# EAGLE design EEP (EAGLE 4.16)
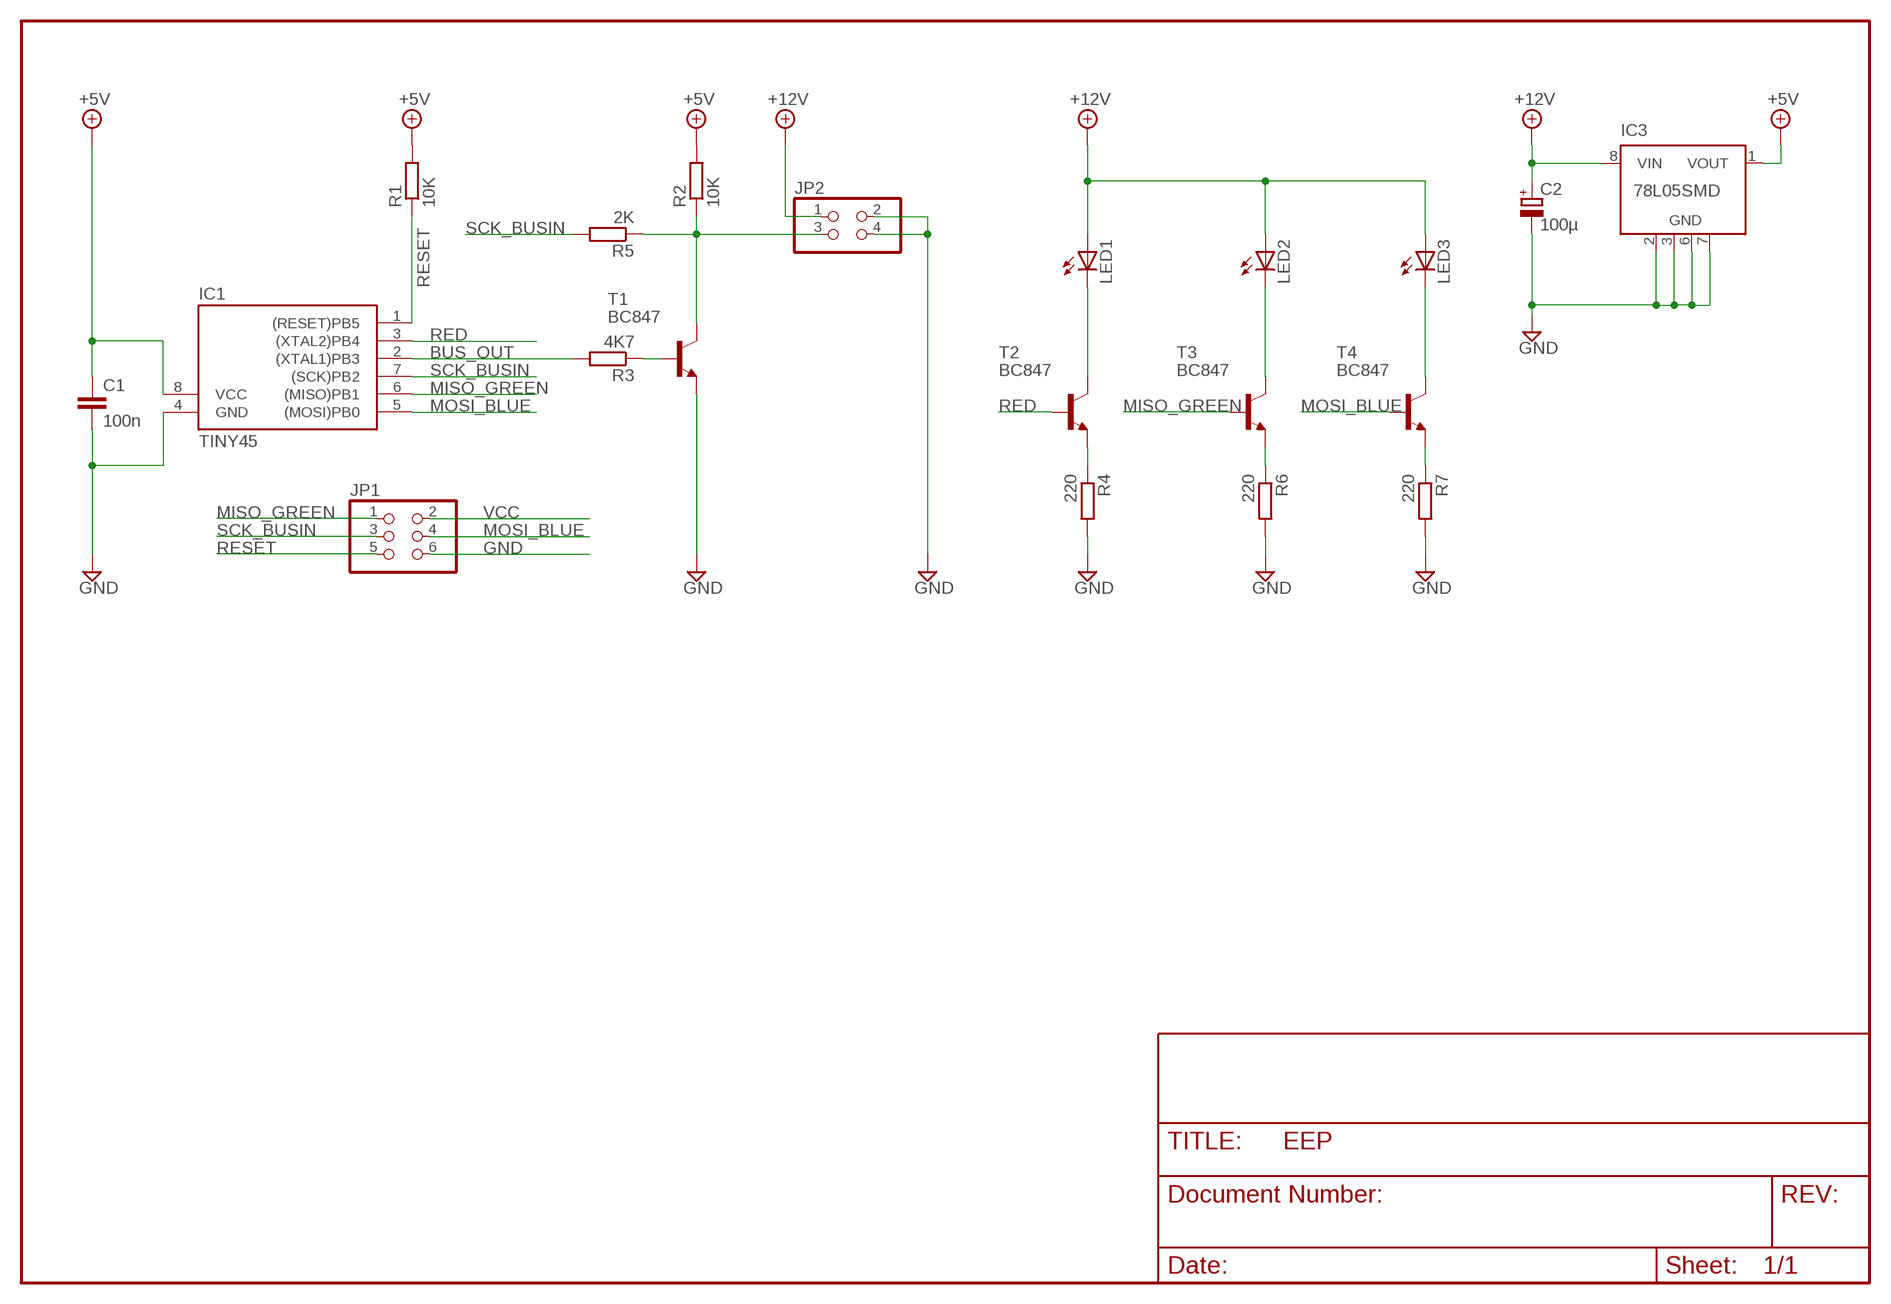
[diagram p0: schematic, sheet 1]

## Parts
C1  100n  C-EUC1206  [C1206]
C2  100µ  CPOL-EU153CLV-0605  [153CLV-0605]
IC1  TINY45  TINY12S  [SOIC8]
IC3  78L05SMD  [SO08]
JP1  PINHD-2X3_2.54-SMD  [2X03SMD]
JP2  PINHD-2X2_2.54-SMD  [2X02SMD]
LED1  LED5MM  [LED5MM]
LED2  LED5MM  [LED5MM]
LED3  LED5MM  [LED5MM]
R1  10K  R-EU_R1206  [R1206]
R2  10K  R-EU_R1206  [R1206]
R3  4K7  R-EU_R1206  [R1206]
R4  220  R-EU_R1206  [R1206]
R5  2K  R-EU_R1206  [R1206]
R6  220  R-EU_R1206  [R1206]
R7  220  R-EU_R1206  [R1206]
T1  BC847  [SOT23]
T2  BC847  [SOT23]
T3  BC847  [SOT23]
T4  BC847  [SOT23]

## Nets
+12V: C2.+ IC3.8(VIN) JP2.1 LED1.A LED2.A LED3.A
BUS_OUT: IC1.2((XTAL1)PB3) R3.2
GND: C1.2 C2.- IC1.4(GND) IC3.2(GND) IC3.3(GND) IC3.6(GND) IC3.7(GND) JP1.6 JP2.2 JP2.4 R4.2 R6.2 R7.2 T1.2(E)
MISO_GREEN: IC1.6((MISO)PB1) JP1.1 T3.1(B)
MOSI_BLUE: IC1.5((MOSI)PB0) JP1.4 T4.1(B)
N$1: LED1.K(C) T2.3(C)
N$2: R4.1 T2.2(E)
N$3: JP2.3 R2.1 R5.1 T1.3(C)
N$4: R6.1 T3.2(E)
N$5: R3.1 T1.1(B)
N$6: R7.1 T4.2(E)
N$7: LED3.K(C) T4.3(C)
N$8: LED2.K(C) T3.3(C)
RED: IC1.3((XTAL2)PB4) T2.1(B)
RESET: IC1.1((RESET)PB5) JP1.5 R1.1
SCK_BUSIN: IC1.7((SCK)PB2) JP1.3 R5.2
VCC: C1.1 IC1.8(VCC) IC3.1(VOUT) JP1.2 R1.2 R2.2 ; supply symbol labelled +5V
Unconnected: IC3.4(NC) IC3.5(NC)

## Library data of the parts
C1 = rcl:C-EU: CAPACITOR, European symbol
C2 = rcl:CPOL-EU: POLARIZED CAPACITOR, European symbol
IC1 = avr-1:TINY12*: MICROCONTROLLER 1 Kbytes FLASH 64 bytes EEPROM
IC3 = linear:78L*SMD: Positive VOLTAGE REGULATOR
JP1 = pinhead-1:PINHD-2X3: PIN HEADER
JP2 = pinhead-1:PINHD-2X2: PIN HEADER
LED1-LED3 = led:LED: LED
R1-R7 = rcl:R-EU_: RESISTOR, European symbol
T1-T4 = transistor:BC847: NPN TRANSISTOR

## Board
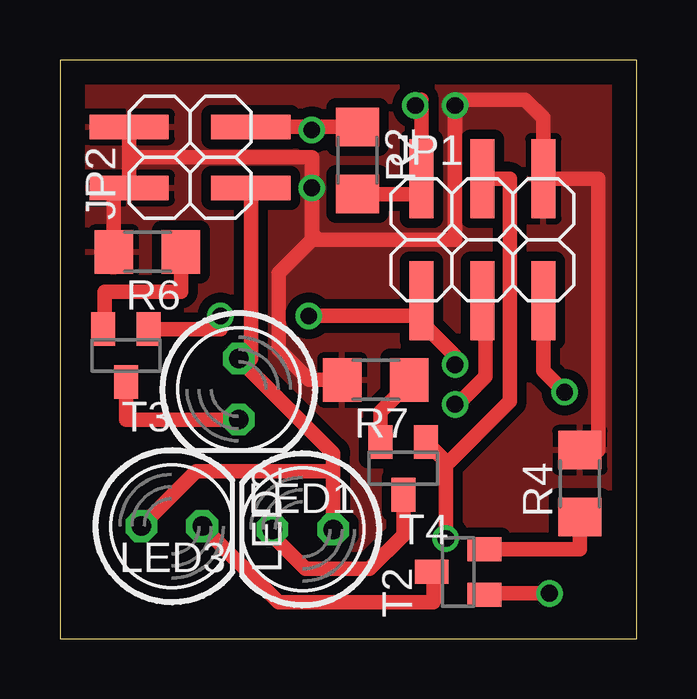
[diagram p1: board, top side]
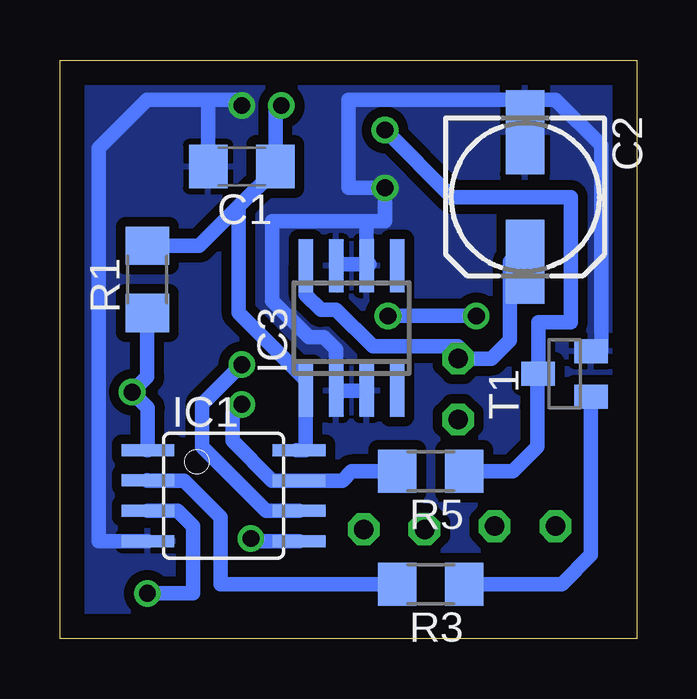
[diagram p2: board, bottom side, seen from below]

Size 24.05 x 24.12 mm. Coordinates in mm from the lower left corner, seen from the top.
Outline: 0,0 24.05,0 24.05,24.12 0,24.12 0,0
Copper layers (1*16): Top 0.035mm / dielectric 1.5mm / Bottom 0.035mm
Design rules "default": minimum track width 10mil, minimum drill 24mil, track to track 16mil, track to pad 12mil, pad to pad 12mil, via to via 12mil, smd to smd 8mil, copper to edge 40mil, drill to drill 8mil, minimum pad ring 10mil, minimum via ring 8mil, stop-mask expansion 4mil, vias tented up to drill 0mil, thermal gap 10mil

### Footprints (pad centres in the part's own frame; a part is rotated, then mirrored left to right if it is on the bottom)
C1206 = smd 1.6 x 1.8: 1 -1.4,0; 2 1.4,0
153CLV-0605 = smd 3.5 x 1.6: + 2.7,0; - -2.7,0
SOIC8 = smd 0.5 x 2.2: 1 -1.905,-3.154; 2 -0.645,-3.154; 3 0.625,-3.154; 4 1.895,-3.154; 5 1.905,3.154; 6 0.635,3.154; 7 -0.635,3.154; 8 -1.905,3.154
SO08 = smd 0.6 x 2.2: 1 -1.905,-2.6; 2 -0.635,-2.6; 3 0.635,-2.6; 4 1.905,-2.6; 5 1.905,2.6; 6 0.635,2.6; 7 -0.635,2.6; 8 -1.905,2.6
2X03SMD = smd 1.016 x 3.302: 1 -1.27,-3.81; 2 -1.27,1.27; 3 1.27,-3.81; 4 1.27,1.27; 5 3.81,-3.81; 6 3.81,1.27
2X02SMD = smd 1.016 x 3.302: 1 -1.27,-3.81; 2 -1.27,1.27; 3 1.27,-3.81; 4 1.27,1.27
LED5MM = drill 0.813 octagon: A -1.27,0; K 1.27,0
R1206 = smd 1.6 x 1.8: 1 -1.4,0; 2 1.4,0
SOT23 = smd 1 x 1.4: 1 -0.95,-1.1; 2 0.95,-1.1; 3 0,1.1

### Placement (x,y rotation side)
C1  16.47,19.68 180 bottom
C2  4.66,18.41 270 bottom
IC1  17.23,5.96 270 bottom
IC3  11.9,12.95 0 bottom
JP1  16.34,17.9 0 top
JP2  4.15,20.06 90 top
LED1  4.66,4.69 0 top
LED2  7.46,10.41 270 top
LED3  10.12,4.57 180 top
R1  20.41,14.98 90 bottom
R2  12.41,19.93 270 top
R3  8.6,2.28 180 bottom
R4  21.68,6.47 90 top
R5  8.6,6.98 180 bottom
R6  3.65,16.12 180 top
R7  13.17,10.79 180 top
T1  3.01,11.04 90 bottom
T2  16.6,2.79 90 top
T3  2.76,11.81 180 top
T4  14.31,7.11 180 top

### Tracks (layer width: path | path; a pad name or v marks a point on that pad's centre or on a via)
+12V
  Top 0.61: JP2.1 7.96,11.68 LED2.A 11.39,7.74 11.39,6.98 | 11.39,6.98 LED3.A | LED1.A 5.68,6.98 11.39,6.98
  Bottom 0.61: LED2.A 7.46,11.55 | LED2.A 7.46,12.19 11.01,12.19 12.54,13.71 13.17,13.71 13.8,14.35 IC3.8 | C2.+ 5.3,15.71 5.3,12.44 6.06,11.68 LED2.A
BUS_OUT
  Bottom 0.61: IC1.2 20.41,6.61 20.41,6.6 18.88,6.6 17.36,5.08 17.36,2.28 R3.2
GND  (via drill 0.7 pad 0.81)
  Top 0.61: JP2.2 2.88,18.66 | JP2.2 JP2.4 | R6.2 2.25,18.79 JP2.2 | JP2.2 2.88,20.06 10.5,20.06 v10.5,18.79 10.5,16.76 | 10.5,16.76 10.5,16.63 16.47,16.63 v16.47,22.22 16.47,22.47 19.39,22.47 20.16,21.71 JP1.6 | R7.2 10.38,10.79 9.11,12.06 9.11,15.23 10.63,16.76 10.5,16.76 | JP1.6 22.44,19.17 22.44,7.87 R4.2 | JP1.6 20.16,19.05
  Bottom 0.61: 4.66,22.47 C2.- | 4.66,22.47 12.03,22.47 12.03,18.79 v10.5,18.79 | T1.2 1.49,11.99 1.49,20.57 3.39,22.47 4.66,22.47 | IC1.4 22.44,4.07 22.44,20.44 20.41,22.47 17.87,22.47 | v16.47,22.22 16.47,22.47 17.87,22.47 | 11.2,15.62 11.14,15.62 | 11.2,15.62 IC3.6 11.27,17.39 | IC3.7 12.47,15.62 11.2,15.62 | IC3.2 12.54,10.41 12.47,10.35 IC3.3 IC3.2 | IC3.2 12.54,12.06 13.04,12.57 13.68,12.57 15.2,14.09 15.2,17.39 11.27,17.39 | 11.27,17.39 10.5,17.39 v10.5,18.79 | v10.5,18.79 10.38,18.79 | C1.2 17.87,22.47
  pour Bottom: 0.6,23.49 0.6,0.63 23.58,0.63 23.58,23.49
  pour Top: 0.6,23.11 0.6,0.5 23.58,0.5 23.58,23.11
MISO_GREEN  (via drill 0.7 pad 0.81)
  Top 0.61: T3.1 6.69,12.91 v6.69,13.46 | 15.07,13.46 JP1.1 | v10.38,13.46 15.07,13.46 | 15.07,13.46 15.07,13.2 16.47,11.81 v16.47,11.42
  Bottom 0.61: v6.69,13.46 v10.38,13.46 | IC1.6 15.46,5.33 18.12,8 18.12,9.77 v16.47,11.42
MOSI_BLUE  (via drill 0.7 pad 0.81)
  Top 0.61: JP1.4 18.76,19.17 18.76,9.9 16.09,7.23 | T4.1 16.09,7.38 16.09,7.23 | v16.09,4.19 16.09,7.23
  Bottom 0.61: IC1.5 16.09,4.06 v16.09,4.19
N$1
  Top 0.61: LED1.K 9.11,1.52 15.58,1.52 15.58,2.71 T2.3
N$2
  Top 0.61: R4.1 21.68,3.74 T2.2
N$3  (via drill 0.7 pad 0.81)
  Top 0.61: R2.1 12.54,21.33 10.5,21.33 | 10.5,21.33 JP2.3 | v10.5,21.2 10.5,21.33
  Bottom 0.61: R5.1 5.17,6.98 4.15,8 4.15,10.92 4.03,11.04 T1.3 4.11,13.2 2.76,13.2 2.76,18.41 7.71,18.41 v10.5,21.2
N$4
  Top 0.61: R6.1 5.04,14.47 1.87,14.47 1.87,12.91 | 1.87,12.91 1.87,12.82 | T3.2 1.87,12.91
N$5
  Bottom 0.61: T1.1 1.91,3.51 3.14,2.28 R3.1
N$6
  Top 0.61: R7.1 14.57,10.67 13.36,9.46 T4.2
N$7
  Top 0.61: T4.3 14.31,4.31 12.92,2.92 10.25,2.92 8.85,4.31 LED3.K
N$8
  Top 0.61: T3.3 2.76,9.14 LED2.K
RED  (via drill 0.7 pad 0.81)
  Top 0.61: T2.1 17.7,1.9 v20.41,1.9
  Bottom 0.61: IC1.3 19.14,5.33 18.5,4.69 18.5,1.9 v20.41,1.9
RESET  (via drill 0.7 pad 0.81)
  Top 0.61: JP1.5 20.16,11.17 v21.04,10.28
  Bottom 0.61: 20.41,7.87 IC1.1 20.39,9.63 v21.04,10.28 | v21.04,10.28 21.17,10.28 | R1.1 20.41,10.92 v21.04,10.28
SCK_BUSIN  (via drill 0.7 pad 0.81)
  Top 0.61: JP1.3 17.74,14.09 17.74,10.92 16.6,9.77 v16.47,9.77
  Bottom 0.61: IC1.7 14.19,6.6 | IC1.7 15.2,6.6 16.85,8.25 16.85,9.39 v16.47,9.77 | R5.2 11.9,6.98 12.28,6.6 IC1.7
VCC  (via drill 0.7 pad 0.81)
  Top 0.61: 15.07,18.53 R2.2 | 15.07,18.53 JP1.2 | 15.07,22.47 v14.82,22.22 15.07,22.22 15.07,18.53
  Bottom 0.61: 14.19,7.87 IC1.8 13.8,7.87 IC3.1 13.8,10.79 16.6,13.58 16.6,18.03 | 16.6,18.03 15.07,19.56 C1.1 15.07,22.22 v14.82,22.22 | R1.2 18.25,16.38 16.6,18.03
